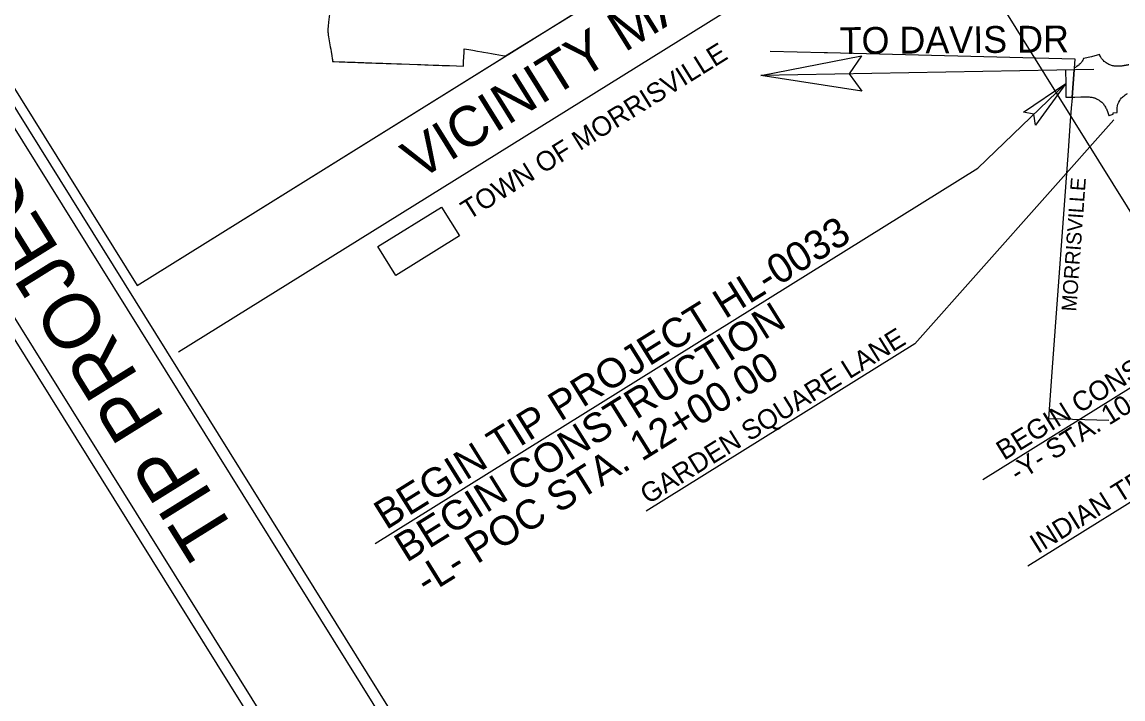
# Model space of a CAD drawing. Extents: x 2038094 to 2053858, y 751760 to 764312.
# Drawn here: x 2043353 to 2046307, y 756547 to 758364 of the extents above; entities that cross this region are included whole.
import ezdxf

# ---------------------------------------------------------------- set-up
doc = ezdxf.new("R2010")
doc.units = 0
for name, color, linetype in [('Old_Level_11', 7, 'Continuous'), ('Old_Level_14', 7, 'Continuous'), ('Old_Level_2', 7, 'Continuous'), ('Old_Level_46', 7, 'Continuous'), ('Prop Shade Light', 7, 'Continuous'), ('Prop Terminator CELL', 7, 'Continuous'), ('Scratch_Level_1', 7, 'Continuous'), ('Sheet Clip Boundary CELL', 7, 'Continuous'), ('Sheet Title CELL', 7, 'Continuous')]:
    doc.layers.add(name, color=color, linetype=linetype)

msp = doc.modelspace()

# ---------------------------------------------------------------- linework, layer by layer
at = {"layer": 'Old_Level_11'}
msp.add_line((2046228.2, 758236.2), (2045334.9, 758220.2), dxfattribs=at)
at = {"layer": 'Old_Level_14'}
for points in [[(2044300.7, 756964.5), (2045916.8, 757971.1), (2046152.9, 758198.4)], [(2046737.4, 758169.4), (2046678.7, 757601.6), (2045930.3, 757135.4)], [(2046743.8, 758163.4), (2046879, 757418.7), (2046051.1, 756903.1)], [(2046282.1, 758101.1), (2045748.5, 757500.5), (2045027.6, 757051.4)]]:
    msp.add_lwpolyline(points, dxfattribs=at)
at = {"layer": 'Old_Level_2'}
for points in [[(2045360.2, 758285.4), (2045504.6, 758281.9)], [(2045504.6, 758281.9), (2045513.5, 758281.6), (2046177.6, 758265.3), (2046169.1, 758148.7), (2046168.8, 758143.4), (2046165.1, 758098.6), (2046159.2, 758017.7), (2046117.9, 757448.8), (2046107, 757300.2), (2046268.8, 757295.2)]]:
    msp.add_lwpolyline(points, dxfattribs=at)
at = {"layer": 'Prop Shade Light'}
for p, q in [((2044650.5, 758272.7), (2044893.1, 758423.7)), ((2046243.5, 758276.5), (2046221.8, 758269.9)), ((2046221.8, 758269.9), (2046200.8, 758265.4)), ((2046175.4, 758235.2), (2046152.2, 758234.8)), ((2046152.2, 758234.9), (2046152.2, 758234.9)), ((2046152.2, 758234.8), (2046152.9, 758198.4)), ((2046170.1, 758162.1), (2046175.4, 758235.2)), ((2046269.1, 758112.8), (2046269, 758112.7)), ((2046269, 758112.7), (2046269.1, 758112.8)), ((2046269.1, 758112.8), (2046280.6, 758116.9)), ((2046280.1, 758119.7), (2046291.1, 758121.3)), ((2046280.6, 758116.9), (2046280.1, 758119.7)), ((2046291.3, 758121.3), (2046291.1, 758121.3)), ((2046291.1, 758121.3), (2046291.3, 758121.3))]:
    msp.add_line(p, q, dxfattribs=at)
for points in [[(2044177.7, 758385.2), (2044175.3, 758363.3), (2044175, 758360), (2044174.7, 758356.6), (2044174.6, 758355), (2044173.4, 758342.2), (2044173.5, 758339.7), (2044173.8, 758336.4), (2044174.1, 758333.5), (2044174.7, 758328.8), (2044175.4, 758324), (2044180.2, 758297.2), (2044181.4, 758290.8), (2044182.7, 758283.6), (2044184.3, 758273.7), (2044184.4, 758272.9), (2044185.4, 758265.6), (2044185.7, 758263.6), (2044186.2, 758258), (2044186.2, 758257.9), (2044190.1, 758257.7), (2044204.1, 758257.2), (2044212.3, 758256.9), (2044219.3, 758256.6), (2044226.3, 758256.4), (2044233.3, 758256.1), (2044240.3, 758255.9), (2044247.3, 758255.6), (2044254.3, 758255.4), (2044255.5, 758255.3), (2044261.3, 758255.1), (2044270, 758254.8), (2044275, 758254.6), (2044291.2, 758254), (2044302.2, 758253.6), (2044312.1, 758253.3), (2044321.3, 758252.9), (2044330.4, 758252.6), (2044343.2, 758252.1), (2044358.5, 758251.6), (2044370.9, 758251.1), (2044413.7, 758249.6), (2044423.2, 758249.3), (2044433.6, 758248.9), (2044440.7, 758248.7), (2044442.6, 758248.6), (2044455.8, 758248.1), (2044461.8, 758248), (2044471.7, 758247.7), (2044480.7, 758247.4), (2044492.2, 758247), (2044499.9, 758246.8), (2044537.1, 758245.6), (2044537.7, 758256.5), (2044539.2, 758283.1), (2044539.7, 758291.8), (2044552.1, 758289.7), (2044562.7, 758287.8), (2044574.8, 758285.7), (2044586.9, 758283.6), (2044591.4, 758282.9), (2044603.2, 758280.8), (2044612.8, 758279.2), (2044616.7, 758278.5), (2044622.6, 758277.5), (2044632.5, 758275.8), (2044642.3, 758274.1), (2044650.5, 758272.7), (2044650.5, 758272.7)], [(2046290.4, 758245), (2046288.1, 758245.1), (2046285.6, 758245.3), (2046283.1, 758245.5), (2046280.7, 758245.9), (2046278.2, 758246.5), (2046275.8, 758247.2), (2046273.6, 758247.9), (2046271.3, 758248.8), (2046268.9, 758249.9), (2046266.3, 758251.2), (2046264.1, 758252.4), (2046261.5, 758254.1), (2046259.4, 758255.7), (2046256.4, 758258.1), (2046254, 758260.3), (2046253, 758261.4), (2046251.2, 758263.5), (2046249.1, 758266.2), (2046247.1, 758269.1), (2046245.9, 758271.3), (2046244.7, 758273.6), (2046243.5, 758276.5)], [(2046200.8, 758265.4), (2046199.7, 758263.2), (2046198.5, 758261), (2046197.2, 758258.9), (2046196, 758257), (2046194.5, 758255.1), (2046193.3, 758253.6), (2046191.3, 758251.5), (2046189.1, 758249.4), (2046187.7, 758248.1), (2046186, 758246.7), (2046183.1, 758244.5), (2046181, 758243.1), (2046179, 758241.9), (2046176.8, 758240.7), (2046175.8, 758240.2)], [(2046306.6, 758246.2), (2046305.6, 758246), (2046303.1, 758245.7), (2046301.2, 758245.4), (2046298.7, 758245.2), (2046296.2, 758245.1), (2046293.7, 758245), (2046291.2, 758245), (2046290.4, 758245)], [(2046175.8, 758240.2), (2046175.4, 758235.2), (2046170.1, 758162.1)], [(2046152.9, 758198.4), (2046152.9, 758198.4), (2046153.5, 758161.8)], [(2046153.5, 758161.8), (2046156, 758161.8), (2046170.1, 758162.1)], [(2046170.1, 758162.1), (2046171.2, 758162.2), (2046177.5, 758162.3), (2046193.1, 758162.6), (2046207.9, 758162.8), (2046210.8, 758162.8), (2046213.3, 758162.7), (2046215.8, 758162.6), (2046218.3, 758162.5), (2046220.8, 758162.2), (2046223.3, 758161.8), (2046225.8, 758161.3), (2046226.2, 758161.2)], [(2046226.2, 758161.2), (2046228.2, 758160.6), (2046230.6, 758159.9), (2046232.9, 758159), (2046235.4, 758157.9), (2046237.6, 758156.8), (2046240.7, 758155), (2046242.9, 758153.6), (2046244.5, 758152.5), (2046247.1, 758150.6), (2046249.7, 758148.3), (2046251.5, 758146.5), (2046253.9, 758143.9), (2046255.4, 758141.8), (2046256.8, 758139.8), (2046258.1, 758137.6), (2046259.7, 758135), (2046260.9, 758132.8), (2046262, 758130.5), (2046263, 758128.2), (2046264.9, 758123.6), (2046269, 758112.7)], [(2046291.3, 758121.3), (2046291.2, 758122.5), (2046290.9, 758125.8), (2046290.8, 758130.1), (2046291, 758133.2), (2046291.8, 758138.8), (2046293.1, 758143), (2046293.8, 758144.8), (2046295.7, 758148.8), (2046297.9, 758152.8), (2046300.2, 758156.4), (2046303, 758159.9), (2046305.1, 758162), (2046307.5, 758164.2), (2046309.6, 758166), (2046312.7, 758168.5), (2046315.5, 758170.1), (2046319.1, 758172)]]:
    msp.add_lwpolyline(points, dxfattribs=at)
msp.add_lwpolyline([(2044307.9, 757761), (2044478.4, 757867.2), (2044526.8, 757789.6), (2044356.3, 757683.4)], close=True, dxfattribs=at)
msp.add_spline([(2046322.4, 758248.7), (2046322, 758248.6), (2046321.4, 758248.5), (2046320.7, 758248.4), (2046320.1, 758248.3), (2046319.4, 758248.2), (2046318.8, 758248.1), (2046318.2, 758248), (2046317.5, 758247.9), (2046316.9, 758247.8), (2046316.2, 758247.7), (2046315.6, 758247.6), (2046314.9, 758247.5), (2046314.3, 758247.4), (2046313.6, 758247.3), (2046313, 758247.2), (2046312.4, 758247.1), (2046311.7, 758247), (2046311.1, 758246.9), (2046310.4, 758246.8), (2046309.8, 758246.7), (2046309.1, 758246.6), (2046308.5, 758246.5), (2046307.8, 758246.4), (2046307.2, 758246.3), (2046306.6, 758246.2)], degree=3, dxfattribs=at)
at = {"layer": 'Prop Terminator CELL'}
for points in [[(2045605.7, 758178.5), (2045334.9, 758220.2), (2045605.5, 758273), (2045571.9, 758224.4)], [(2046039.5, 758121.5), (2046152.9, 758198.4), (2046071.7, 758087), (2046067.5, 758116.2)]]:
    msp.add_lwpolyline(points, close=True, dxfattribs=at)
at = {"layer": 'Scratch_Level_1'}
msp.add_lwpolyline([(2045946.3, 758464.5), (2046501.4, 757573.2), (2047629.6, 758276), (2047220.5, 759009), (2047136.3, 758956.5), (2047077, 759051.7), (2046934.2, 758962.7), (2046881.6, 759047.1)], close=True, dxfattribs=at)
at = {"layer": 'Sheet Clip Boundary CELL'}
msp.add_lwpolyline([(2043662.2, 757657.1), (2046007.5, 759117.9), (2044949.5, 760816.6), (2042604.1, 759355.8)], close=True, dxfattribs=at)
at = {"layer": 'Sheet Title CELL'}
for p, q in [((2045150.5, 755218.4), (2042501.7, 759470.9)), ((2045711.9, 754260.3), (2042476.2, 759455)), ((2043662.2, 757657.1), (2046007.5, 759117.9)), ((2043773.4, 757478.5), (2046118.7, 758939.3))]:
    msp.add_line(p, q, dxfattribs=at)
for points in [[(2042205.7, 759321.9), (2045473.1, 754076.3)], [(2042205.7, 759321.9), (2045473.1, 754076.3)], [(2042247.1, 759312.3), (2045482.7, 754117.6)]]:
    msp.add_lwpolyline(points, dxfattribs=at)

# ---------------------------------------------------------------- texts
at = {"layer": 'Old_Level_14'}
for s, height, p in [('TOWN OF MORRISVILLE', 52.501, (2044551.6, 757831.5)), ('BEGIN TIP PROJECT HL-0033', 78.751, (2044330.2, 756999.6)), ('BEGIN CONSTRUCTION', 52.501, (2045987.7, 757186.2)), ('BEGIN CONSTRUCTION', 78.751, (2044384.8, 756911.9)), ('GARDEN SQUARE LANE', 52.501, (2045032.6, 757068.2)), ('-L- POC STA. 12+00.00', 78.751, (2044439.4, 756824.3)), ('-Y- STA. 10+20.00', 52.501, (2046024.1, 757127.8)), ('INDIAN TRAIL GREENWAY', 52.501, (2046078.2, 756935.4))]:
    msp.add_text(s, height=height, rotation=31.918, dxfattribs=at).set_placement(p)
at = {"layer": 'Old_Level_2'}
msp.add_text('MORRISVILLE', height=40, rotation=85.8401, dxfattribs=at).set_placement((2046181.1, 757586))
at = {"layer": 'Old_Level_46'}
msp.add_text('TO DAVIS DR', height=72, rotation=0.4577, dxfattribs=at).set_placement((2045546.7, 758277.6))
at = {"layer": 'Sheet Title CELL'}
for s, height, rotation, p in [('VICINITY MAP', 108, 31.9164, (2044417.7, 757937.4)), ('TIP PROJECT:', 150, 121.918, (2043933.3, 756986.5))]:
    msp.add_text(s, height=height, rotation=rotation, dxfattribs=at).set_placement(p)

doc.saveas('drawing.dxf')
